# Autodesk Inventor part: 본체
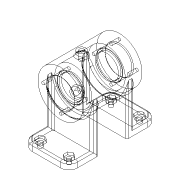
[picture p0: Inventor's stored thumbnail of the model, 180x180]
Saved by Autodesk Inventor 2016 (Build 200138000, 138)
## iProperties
Created: 2017-02
Part Number: 본체
Material: 일반
Document SubType Name: Modeling
Designer: H
Density: 1 g/cm^3
Appearance: 기본값
Author: H
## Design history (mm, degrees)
sketch "스케치2"
  geometry: C1 r 27 at (0, 0); 1 further point
  constraints: 1 centre point, 1 coincident
  dimensions: "d0" = 54 diameter of C1
extrude "돌출1" new body sketch "스케치2" stored distance "d1" = 70; taper "d2" = 0 deg
sketch "스케치4"
  geometry: L1 (-27, -35)-(27, -35) reference; L2 (27, 35)-(-27, 35) reference; L3 (0, 0)-(-60, 0); L4 (-60, 0)-(-60, 52); L5 (-60, 52)-(-52, 52); L6 (-52, 52)-(-52, 17); L7 (-52, 17)-(-60, 17) reference; L8 (-60, 17)-(-60, 52); L9 (27, -35)-(27, 35) reference; L10 (-60, -52)-(-52, -52); L11 (-52, -52)-(-52, -17); L12 (-52, -17)-(-60, -17); L13 (-60, -17)-(-60, -52)
  constraints: 20 end point, 4 symmetric about line, 3 horizontal, 2 vertical, 1 collinear, 1 perpendicular, 1 point on line
  dimensions: "d11" = 60 distance of L3.start L3.end; "d12" = 52 distance of L3.end L4.end; "d13" = 8 distance of L4.end L5.end
extrude "돌출2" join sketch "스케치4" stored distance "d17" = 54; taper "d18" = 0 deg
sketch "스케치7"
  geometry: L1 (20.591, 15)-(32, 15); L2 (32, 15)-(32, 10); L3 (32, 10)-(27, 10); L4 (-27, -35)-(27, -35) reference; L5 (27, 35)-(-27, 35) reference; L6 (27, -35)-(27, 35) reference; L7 (20.591, 15)-(20.591, 10); L8 (27, 10)-(20.591, 10); 2 further points
  constraints: 10 end point, 2 perpendicular, 1 horizontal, 1 vertical
  dimensions: "d27" = 25 vertical distance of L2.end point (27, 35); "d28" = 5 distance from line of L6 L2.end; "d30" = 11.40892 distance of L1.start L1.end
revolve "회전1" sketch "스케치7" stored, may be unused: angle "d31" = 90 deg
sketch "스케치8"
  geometry: L1 (-52, -52)-(-52, -60) reference; L2 (-52, -60)-(-17, -60) reference; L3 (-17, -60)-(-17, -52) reference; L4 (-17, -52)-(-52, -52) reference; L5 (-17, -52)-(-25, -52); L6 (-17, -52)-(-17, 0); L7 (-17, 0)-(-25, 0); L8 (-25, 0)-(-25, -52); 1 further point
  constraints: 8 end point, 1 collinear, 1 horizontal, 1 perpendicular, 1 point on line, 1 vertical
  dimensions: "d33" = 8 distance of L6.end L7.end; "d36" = 52 distance of L3.end L6.end
extrude "돌출3" join sketch "스케치8" distance "d34" = 54; taper "d35" = 0 deg
sketch "스케치10"
  geometry: C1 r 16 at (0, 0); 1 further point
  constraints: 1 centre point, 1 coincident
  dimensions: "d37" = 32 diameter of C1
extrude "돌출4" cut sketch "스케치10" distance "d38" = 12; taper "d39" = 0 deg
sketch "스케치11"
  geometry: C1 r 14 at (0, 0); 1 further point
  constraints: 1 centre point, 1 coincident
  dimensions: "d40" = 28 diameter of C1
extrude "돌출5" cut sketch "스케치11" distance "d41" = 3; taper "d42" = 0 deg
sketch "스케치15" dims "d52" = 42
  geometry: 3 further points
  constraints: 1 coincident, 1 vertical alignment, 2 other
hole "구멍1" sketch "스케치15" at (0, 21) diameter "d53" = 3.242; stored, may be unused: countersink angle "d57" = 90 deg, drill point angle "d59" = 118 deg; dims "d54" = 8, "d55" = 4, "d56" = 2, "d58" = 10
sketch "스케치17"
  geometry: C1 r 5 at (0, 0) reference; 2 further points
  constraints: 1 coincident
hole "구멍2" sketch "스케치17" at (0, 0) diameter "d63" = 5.188; stored, may be unused: countersink angle "d67" = 90 deg, drill point angle "d69" = 118 deg; dims "d64" = 20, "d65" = 4, "d66" = 2, "d68" = 20
sketch "스케치18"
  geometry: L1 (0, 0)-(-18.991, -29.244); L2 (0, 0)-(0, -30.49); L3 (0, 0)-(-5.032, 3.268); L4 (-5.032, 3.268)-(-21.371, -21.892); L5 (-21.371, -21.892)-(-16.339, -25.16); C1 r 1.621 at (-21, 0) reference; C2 r 1.621 at (0, -21) reference; C3 r 1.621 at (21, 0) reference; C4 r 1.621 at (0, 21) reference; C5 r 16 at (0, 0) reference; C6 r 27 at (0, 0) reference; 1 further point
  constraints: 10 end point, 2 perpendicular, 1 point on line, 1 vertical
  dimensions: "d70" = 33 deg angle of L2 L1; "d71" = 30 distance of L3.end L4.end; "d72" = 12 diameter of L4.end L1; "d73" = 12 diameter of L3.end L1
revolve "회전2" sketch "스케치18" stored, may be unused: angle "d74" = 90 deg
sketch "스케치19"
  geometry: C1 r 22 at (0, 0); 1 further point
  constraints: 1 centre point, 1 coincident
  dimensions: "d75" = 44 diameter of C1
extrude "돌출9" cut sketch "스케치19" distance "d76" = 40; taper "d77" = 0 deg
sketch "스케치20"
  geometry: 2 further points
  constraints: 1 coincident
hole "구멍3" sketch "스케치20" at (0, 0) diameter "d78" = 5.188; stored, may be unused: countersink angle "d82" = 90 deg, drill point angle "d84" = 118 deg; dims "d79" = 20, "d80" = 4, "d81" = 2, "d83" = 20
fillet "모깎기1" dims "d85" = 10
sketch "스케치22" dims "d86" = 9
  geometry: L1 (44, 27)-(10, 27) reference; L2 (54, -8)-(54, 17) reference; L3 (0, -8)-(54, -8) reference; L4 (0, 17)-(0, -8) reference; L5 (0, -42)-(0, -67) reference; L6 (54, -42)-(0, -42) reference; L7 (54, -67)-(54, -42) reference; L8 (10, -77)-(44, -77) reference; L9 (5.5, 19.598)-(10, 22.196); L10 (10, 22.196)-(14.5, 19.598); L11 (14.5, 19.598)-(14.5, 14.402); L12 (14.5, 14.402)-(10, 11.804); L13 (10, 11.804)-(5.5, 14.402); L14 (5.5, 14.402)-(5.5, 19.598); A1 r 10 centre (10, 17) between (10, 27) and (0, 17) reference; A2 r 10 centre (44, 17) between (54, 17) and (44, 27) reference; A3 r 10 centre (10, -67) between (0, -67) and (10, -77) reference; A4 r 10 centre (44, -67) between (44, -77) and (54, -67) reference; 4 further points
  constraints: 12 end point, 2 coincident, 1 horizontal alignment, 1 midpoint, 1 vertical alignment, 15 other
extrude "돌출10" cut sketch "스케치22" distance "d87" = 3; taper "d88" = 0 deg
sketch "스케치23"
  geometry: L1 (44, 27)-(10, 27) reference; L2 (54, -8)-(54, 17) reference; L3 (0, -8)-(54, -8) reference; L4 (0, 17)-(0, -8) reference; C1 r 2.5 at (10, 17); A1 r 10 centre (10, 17) between (10, 27) and (0, 17) reference; A2 r 10 centre (44, 17) between (54, 17) and (44, 27) reference; 1 further point
  constraints: 1 centre point, 1 coincident
  dimensions: "d89" = 5 diameter of C1
extrude "돌출11" cut sketch "스케치23" stored distance "d90" = 3; taper "d91" = 0 deg
fillet "모깎기2" dims "d92" = 2
fillet "모깎기3" dims "d93" = 2
fillet "모깎기4" dims "d94" = 2
fillet "모깎기5" dims "d95" = 2
chamfer "모따기1" distance "d96" = 1; stored, may be unused: second distance "d97" = 2, angle "d98" = 45 deg
fillet "모깎기6" dims "d99" = 0.3
node "솔리드1"
mirror "대칭1"
pattern_circular "원형 패턴1" dims angle "d61" = 360 deg
mirror "대칭3"
mirror "대칭4"
mirror "대칭5"
mirror "대칭6"
node "투영된 루프2"
node "투영된 루프5"
node "투영된 루프6"
node "투영된 루프7"
node "투영된 루프8"
node "투영된 루프9"
node "투영된 루프10"
